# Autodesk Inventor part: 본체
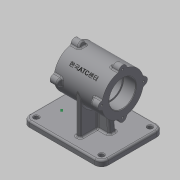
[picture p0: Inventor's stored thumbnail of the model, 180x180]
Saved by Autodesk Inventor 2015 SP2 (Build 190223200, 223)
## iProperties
Created: 2015-12
Part Number: 본체
Material: 일반
Document SubType Name: Modeling
Designer: AMC
Density: 1 g/cm^3
Appearance: 기본값
Author: AMC
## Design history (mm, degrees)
sketch "스케치1"
  geometry: L1 (-80, 55)-(60, 55); L2 (60, 55)-(60, -55); L3 (60, -55)-(-80, -55); L4 (-80, -55)-(-80, 55); 1 further point
  constraints: 8 end point, 2 parallel, 1 horizontal, 1 perpendicular
  dimensions: "d0" = 140 distance of L1.start L1.end; "d1" = 110 distance of L1.end L2.end; "d2" = 55 distance from line of point (0, 0) L1; "d3" = 80 distance from line of L4 point (0, 0)
extrude "돌출1" new body sketch "스케치1" distance "d4" = 10; taper "d5" = 0 deg
sketch "스케치2"
  geometry: 1 further point
sketch "스케치3"
  geometry: L1 (55, 0)-(-55, 0) reference; C1 r 37 at (0, 80); 2 further points
  constraints: 1 centre point, 1 midpoint, 1 vertical alignment
  dimensions: "d6" = 74 diameter of C1; "d7" = 80 distance from line of L1 C1.centre
extrude "돌출2" join sketch "스케치3" stored distance "d8" = 85; taper "d9" = 0 deg
sketch "스케치4"
  geometry: L1 (-4, 37)-(4, 37); L2 (4, 37)-(4, -37); L3 (4, -37)-(-4, -37); L4 (-4, -37)-(-4, 37); L5 (-4, 37)-(4, -37); L6 (4, 37)-(-4, -37); 1 further point
  constraints: 12 end point, 2 midpoint, 2 parallel, 1 horizontal, 1 perpendicular
  dimensions: "d11" = 8 distance of L1.start L1.end; "d12" = 74 distance of L1.end L2.end
extrude "돌출3" join sketch "스케치4" distance "d13" = 70; taper "d14" = 0 deg
sketch "스케치5"
  geometry: L1 (-25, 10)-(-21.08, 41.923); L2 (80, 10)-(-60, 10) reference; 1 further point
  constraints: 2 end point, 1 point on line
  dimensions: "d15" = 97 deg angle of L2 L1; "d16" = 25 horizontal distance of L1.start point (0, 0)
feature "리브1" sketch "스케치5" dims "d17" = 1, "d18" = 12, "d19" = 0, "d20" = 0, "d21" = 1, "d22" = 1
sketch "스케치6"
  geometry: L1 (-42.5, 103.5)-(-20.5, 103.5); L2 (-20.5, 103.5)-(-20.5, 101); L3 (-20.5, 101)-(20.5, 101); L4 (20.5, 101)-(20.5, 103.5); L5 (20.5, 103.5)-(42.5, 103.5); L6 (42.5, 103.5)-(42.5, 80); L7 (42.5, 80)-(-42.5, 80); L8 (-42.5, 80)-(-42.5, 103.5); L9 (-60, 0)-(80, 0) reference; L10 (-42.5, 117)-(-42.5, 43) reference; L11 (42.5, 43)-(42.5, 117) reference; 1 further point
  constraints: 16 end point, 3 perpendicular, 2 collinear, 2 horizontal, 2 parallel, 1 point on line, 1 vertical
  dimensions: "d23" = 47 diameter of L5 L7; "d24" = 42 diameter of L3 L7; "d25" = 80 distance between parallel lines of L9 L7; "d26" = 22 distance of L4.end L5.end; "d27" = 22 distance of L1.start L1.end
revolve "회전1" sketch "스케치6" stored, may be unused: angle "d28" = 90 deg
fillet "모깎기1" dims "d29" = 0.3
chamfer "모따기1" distance "d30" = 1; stored, may be unused: second distance "d31" = 2, angle "d32" = 45 deg
sketch "스케치7"
  geometry: C1 r 7 at (-37, 0); 2 further points
  constraints: 2 horizontal alignment, 1 centre point, 1 other
  dimensions: "d33" = 14 diameter of C1
extrude "돌출4" join sketch "스케치7" distance "d34" = 15; taper "d35" = 0 deg
sketch "스케치8"
  geometry: L1 (42.5, 117)-(-27.5, 117) reference; L2 (-27.5, 116.338)-(-27.5, 124) reference; L3 (-42.5, 124)-(-27.5, 124) reference; L4 (-27.5, 117)-(-30.048, 124); L5 (-54.623, 80)-(55.411, 80); L6 (-60, 0)-(80, 0) reference; 1 further point
  constraints: 4 end point, 1 horizontal, 1 point on line
  dimensions: "d36" = 110 deg angle of L1 L4; "d37" = 80 distance between parallel lines of L6 L5
revolve "회전2" stored, may be unused: angle "d38" = 30 deg
fillet "모깎기2" dims "d39" = 3
sketch "스케치9"
  geometry: A1 r 37 centre (80, 0) between (115.862, 9.104) and (89.104, 35.863) reference; 3 further points
  constraints: 2 horizontal alignment, 4 other
hole "구멍1" sketch "스케치9" at (117, 0) diameter "d43" = 3.242; stored, may be unused: countersink angle "d47" = 90 deg, drill point angle "d49" = 118 deg; dims "d44" = 9, "d45" = 4, "d46" = 2, "d48" = 11
fillet "모깎기3" dims "d53" = 3
fillet "모깎기4" dims "d54" = 3
fillet "모깎기5" dims "d55" = 3
fillet "모깎기6" dims "d56" = 12
hole "구멍2" diameter "d59" = 8; stored, may be unused: countersink angle "d63" = 90 deg, drill point angle "d65" = 118 deg; dims "d57" = 10, "d58" = 10, "d60" = 9, "d61" = 4, "d62" = 2, "d64" = 11
chamfer "모따기2" distance "d72" = 1; stored, may be unused: second distance "d73" = 2, angle "d74" = 45 deg
fillet "모깎기7" dims "d75" = 3
node "작업 평면2"
  node "작업 평면1"
sketch "스케치10"
  geometry: L1 (-25, 3.5)-(25, 3.5); L2 (25, 3.5)-(25, -3.5); L3 (25, -3.5)-(-25, -3.5); L4 (-25, -3.5)-(-25, 3.5); L5 (-25, 0)-(25, 0); L6 (0, 3.5)-(0, -3.5); L7 (-108, 0)-(88, 0) reference; 1 further point
  constraints: 4 end point, 4 midpoint, 1 collinear, 1 point on line, 2 other
  dimensions: "d77" = 50 distance of L1.start L1.end; "d78" = 7 distance of L1.end L2.end
feature "엠보싱1" sketch "스케치10" dims "d0" = 140, "d1" = 110, "d2" = 55, "d3" = 80, "d11" = 8, "d12" = 74, "d79" = 0.5, "d80" = 0
sketch "스케치11"
  geometry: 1 further point
node "솔리드1"
mirror "대칭1"
mirror "대칭2"
pattern_circular "원형 패턴1" dims "d41" = 360 deg
pattern_circular "원형 패턴2" dims angle "d51" = 360 deg
mirror "대칭3"
pattern_linear "직사각형 패턴1" dims "d68" = 116, "d71" = 86
node "작업축2"
other parameters: "d76" = -45 deg
